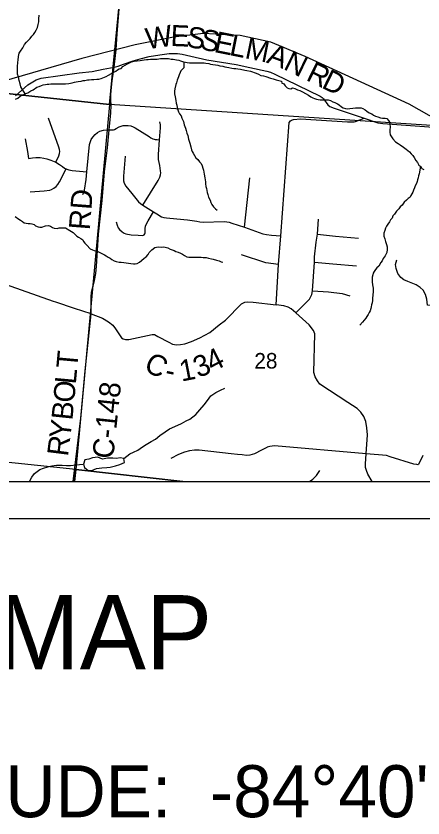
# Model space of a CAD drawing. Extents: x 0 to 34, y 0 to 22.
# Drawn here: x 5.92 to 7.016, y 13.194 to 15.353 of the extents above; entities that cross this region are included whole.
import ezdxf

# ---------------------------------------------------------------- set-up
doc = ezdxf.new("R2010")
doc.units = 0
for name, color, linetype in [('Default', 7, 'Continuous'), ('GM_X_County_Road', 7, 'Continuous'), ('GM_X_County_Road_Text', 7, 'Continuous'), ('GM_X_Minor_Lake', 7, 'Continuous'), ('GM_X_Minor_River', 7, 'Continuous'), ('GM_X_Rail_Line', 7, 'Continuous'), ('GM_X_Section', 7, 'Continuous'), ('GM_X_Section_Text', 7, 'Continuous'), ('GM_X_State_Route', 7, 'Continuous'), ('GM_X_Township_Road', 7, 'Continuous'), ('SH_Data', 7, 'Continuous'), ('SH_Text', 7, 'Continuous')]:
    doc.layers.add(name, color=color, linetype=linetype)

msp = doc.modelspace()

# ---------------------------------------------------------------- linework, layer by layer
at = {"layer": 'Default'}
for points in [[(6.3691, 14.1), (7.0916, 14.1), (7.1496, 15.0512), (6.1715, 15.1151), (6.0802, 14.1319)], [(5.0677, 14.1), (6.0771, 14.1), (6.0802, 14.1319), (5.0822, 14.236)], [(6.0771, 14.1), (6.3691, 14.1), (6.0802, 14.1319)]]:
    msp.add_lwpolyline(points, close=True, dxfattribs=at)
at = {"layer": 'GM_X_County_Road'}
for points in [[(6.1223, 14.5512), (6.122, 14.5815), (6.1219, 14.5974), (6.1229, 14.6095), (6.1261, 14.6238), (6.1306, 14.6408), (6.1344, 14.6594), (6.1364, 14.6792), (6.139, 14.7219), (6.1416, 14.7661), (6.1513, 14.8563), (6.1574, 14.9337), (6.1655, 14.9978), (6.1706, 15.047), (6.1746, 15.0922), (6.1756, 15.112), (6.1752, 15.1286), (6.175, 15.1473), (6.1758, 15.1569), (6.1768, 15.1663), (6.1837, 15.2151), (6.1889, 15.2618), (6.1923, 15.305), (6.1982, 15.3827)], [(6.1837, 15.2151), (6.1945, 15.218), (6.2094, 15.2237), (6.2348, 15.2322), (6.2536, 15.2382), (6.2778, 15.2439), (6.3068, 15.2486), (6.3324, 15.2518), (6.3429, 15.2523), (6.3542, 15.2518), (6.367, 15.2507), (6.3903, 15.2447), (6.4333, 15.2349), (6.5127, 15.2229), (6.549, 15.2147), (6.5954, 15.2048), (6.6052, 15.2022), (6.6164, 15.1966), (6.7389, 15.1368), (6.7445, 15.134), (6.7479, 15.1305), (6.7592, 15.1142), (6.7651, 15.1091), (6.7768, 15.105), (6.8572, 15.078), (6.8942, 15.0655), (6.9074, 15.0636), (7.0696, 15.0521)], [(5.9183, 15.1385), (5.9517, 15.1682), (5.9737, 15.1813), (5.9868, 15.1855), (6.0896, 15.2002), (6.1243, 15.2039), (6.1539, 15.2098), (6.1837, 15.2151)], [(6.62, 14.5755), (6.6265, 14.6841), (6.6333, 14.7609), (6.6554, 15.0661), (6.659, 15.0706), (6.6619, 15.0729), (6.6667, 15.0741), (6.6861, 15.0762), (6.8128, 15.0683), (6.8303, 15.0685), (6.8341, 15.0693), (6.8572, 15.078)], [(6.1223, 14.5512), (6.1526, 14.5392), (6.1683, 14.5301), (6.1802, 14.5207), (6.1879, 14.5106), (6.2032, 14.487), (6.2081, 14.4835), (6.2141, 14.4822), (6.2232, 14.4819), (6.2866, 14.4958), (6.2927, 14.4953), (6.3016, 14.4905), (6.3308, 14.4745), (6.3413, 14.4697), (6.3515, 14.4675), (6.3622, 14.4684), (6.374, 14.4704), (6.392, 14.4767), (6.4143, 14.4864), (6.4416, 14.5005), (6.467, 14.5212), (6.4839, 14.5344), (6.5273, 14.5781), (6.5359, 14.5823), (6.5432, 14.5834), (6.5585, 14.5822), (6.62, 14.5755)], [(6.8786, 14.1), (6.8673, 14.1199), (6.8638, 14.1291), (6.8614, 14.1372), (6.861, 14.1474), (6.8629, 14.1744), (6.8665, 14.2251), (6.8649, 14.2445), (6.862, 14.2613), (6.8564, 14.2748), (6.8488, 14.2864), (6.8381, 14.2963), (6.8136, 14.3122), (6.7375, 14.3622), (6.7314, 14.3711), (6.7254, 14.3816), (6.7215, 14.3934), (6.7242, 14.4977), (6.7211, 14.5064), (6.7092, 14.5214), (6.6736, 14.554), (6.6607, 14.565), (6.6527, 14.5691), (6.6414, 14.5728), (6.62, 14.5755)], [(6.0736, 14.1), (6.0945, 14.2699), (6.1055, 14.3973), (6.1223, 14.5512)]]:
    msp.add_lwpolyline(points, dxfattribs=at)
at = {"layer": 'GM_X_Minor_Lake'}
for points in [[(6.1526, 14.1602), (6.1401, 14.1651), (6.1257, 14.1636), (6.1157, 14.1597), (6.1046, 14.1577), (6.1009, 14.1463)], [(6.1009, 14.1464), (6.1041, 14.1372), (6.1141, 14.129), (6.124, 14.1298), (6.1367, 14.1348), (6.1504, 14.1364), (6.1637, 14.1371), (6.1733, 14.1388), (6.1874, 14.1422), (6.1989, 14.1453), (6.2116, 14.1511), (6.2096, 14.1618), (6.1998, 14.1632), (6.1898, 14.1615), (6.18, 14.1622), (6.1663, 14.1622), (6.1526, 14.1602)]]:
    msp.add_lwpolyline(points, dxfattribs=at)
at = {"layer": 'GM_X_Minor_River'}
for points in [[(5.9444, 15.1434), (5.9325, 15.162), (5.9305, 15.1704), (5.9282, 15.1796), (5.9258, 15.1892), (5.9238, 15.1969), (5.9234, 15.206), (5.9234, 15.2166), (5.9242, 15.2291), (5.9251, 15.2344), (5.9262, 15.2443), (5.9284, 15.2529), (5.9312, 15.2581), (5.9376, 15.2678), (5.9425, 15.276), (5.948, 15.2826), (5.9528, 15.2882), (5.9575, 15.2926), (5.9622, 15.2985), (5.967, 15.3036), (5.9706, 15.3085), (5.9742, 15.3152), (5.9775, 15.3223), (5.9793, 15.3298), (5.9807, 15.3374), (5.9813, 15.3453), (5.982, 15.3555)], [(5.9185, 15.1294), (5.9246, 15.1319), (5.9309, 15.137), (5.939, 15.1412), (5.9459, 15.144), (5.9509, 15.1465), (5.9598, 15.1512), (5.9656, 15.1544), (5.9757, 15.1613), (5.9815, 15.163), (5.9877, 15.1658), (5.993, 15.1675), (5.9988, 15.1684), (6.0037, 15.1694), (6.0083, 15.1696), (6.0136, 15.1702), (6.0212, 15.1703), (6.0258, 15.1702), (6.0307, 15.1704), (6.0368, 15.1705), (6.0455, 15.1706), (6.0531, 15.1707), (6.0615, 15.1712), (6.0703, 15.1732), (6.0772, 15.1745), (6.0818, 15.1754), (6.0871, 15.1768), (6.0948, 15.178), (6.1001, 15.179), (6.1047, 15.1796), (6.112, 15.1812), (6.1165, 15.1815), (6.1226, 15.182), (6.1295, 15.1822), (6.1371, 15.1827), (6.1424, 15.1828), (6.1485, 15.1845), (6.1578, 15.1884), (6.1624, 15.1901), (6.1686, 15.1937), (6.1763, 15.198), (6.1814, 15.2009), (6.188, 15.2048), (6.1926, 15.2081), (6.1976, 15.2106), (6.2026, 15.2119), (6.2074, 15.2171), (6.2132, 15.2211), (6.2201, 15.2246), (6.2255, 15.2267), (6.231, 15.2299)], [(6.231, 15.2299), (6.2382, 15.2316), (6.2455, 15.2321), (6.2542, 15.2333), (6.2596, 15.2339), (6.2649, 15.2352), (6.271, 15.2358), (6.2756, 15.236), (6.2821, 15.2365), (6.2881, 15.2367), (6.2931, 15.2365), (6.2995, 15.2371), (6.3041, 15.2377), (6.3091, 15.2383), (6.3155, 15.2388), (6.3307, 15.2383), (6.3371, 15.2373), (6.3432, 15.2367), (6.3519, 15.2353), (6.3579, 15.2339), (6.3628, 15.2322), (6.3681, 15.2309), (6.376, 15.2291), (6.3809, 15.2278), (6.3869, 15.2272), (6.3918, 15.2267), (6.399, 15.2268), (6.4055, 15.2269), (6.4142, 15.227), (6.426, 15.2266), (6.4309, 15.2261), (6.4388, 15.225), (6.4434, 15.2237), (6.4498, 15.2228), (6.4566, 15.2214), (6.4634, 15.2204), (6.4686, 15.2187), (6.4762, 15.2177), (6.4822, 15.2159), (6.4932, 15.2144), (6.5007, 15.2126), (6.5064, 15.2117), (6.5117, 15.2115), (6.517, 15.2109), (6.5245, 15.2095), (6.5358, 15.2072), (6.5415, 15.2063), (6.5513, 15.2044), (6.5562, 15.2027), (6.5614, 15.2007), (6.5667, 15.199), (6.573, 15.1968), (6.579, 15.1932), (6.5865, 15.1918), (6.5926, 15.1901), (6.6049, 15.1855), (6.6121, 15.1841), (6.6204, 15.1815), (6.6271, 15.1798), (6.635, 15.1776), (6.6352, 15.1723), (6.6401, 15.171), (6.6445, 15.1651), (6.6496, 15.16), (6.6541, 15.1579), (6.6594, 15.157), (6.664, 15.1595), (6.6704, 15.1581), (6.6775, 15.1545), (6.6843, 15.1523), (6.6914, 15.1491), (6.6992, 15.1446), (6.7074, 15.1398), (6.7133, 15.1358), (6.7189, 15.1329), (6.7234, 15.1309), (6.729, 15.1295), (6.7336, 15.1286), (6.7392, 15.1277), (6.7442, 15.1271), (6.7495, 15.1273), (6.7552, 15.1275), (6.7601, 15.1273), (6.7669, 15.1256), (6.7728, 15.1223), (6.7781, 15.1198), (6.7852, 15.1162), (6.79, 15.1137), (6.7967, 15.1089), (6.8011, 15.1061), (6.8068, 15.1037), (6.8132, 15.1027), (6.8185, 15.1036), (6.8265, 15.1049), (6.8338, 15.1061), (6.8448, 15.1061), (6.8494, 15.106), (6.8542, 15.1043), (6.8598, 15.1003), (6.8646, 15.0967), (6.8705, 15.092)], [(6.3715, 15.2301), (6.3715, 15.2135), (6.3634, 15.2056), (6.3617, 15.2007), (6.3589, 15.1951), (6.3575, 15.1895), (6.3534, 15.1801), (6.3517, 15.1733), (6.35, 15.1685), (6.3477, 15.1571), (6.3463, 15.1511), (6.3468, 15.1435), (6.3481, 15.1351), (6.35, 15.1259), (6.3513, 15.1183), (6.3526, 15.1129), (6.3539, 15.1064), (6.3556, 15.1006), (6.3569, 15.0953), (6.3602, 15.0898), (6.3645, 15.0844), (6.3658, 15.0783), (6.3705, 15.069), (6.3728, 15.0602), (6.3759, 15.0509), (6.3776, 15.0444), (6.38, 15.0379), (6.3824, 15.0309), (6.3844, 15.0214), (6.3875, 15.011), (6.3901, 15.0007), (6.3925, 14.993), (6.3943, 14.9884), (6.3964, 14.9837), (6.4007, 14.9775), (6.4039, 14.9709), (6.4091, 14.9666), (6.4134, 14.9607), (6.4182, 14.956), (6.4207, 14.9495), (6.4227, 14.9433), (6.4241, 14.9383), (6.4264, 14.9276), (6.4283, 14.9177), (6.4292, 14.9123), (6.4298, 14.907), (6.43, 14.9013), (6.4309, 14.8936), (6.4322, 14.8887), (6.4332, 14.8829), (6.4345, 14.8776), (6.4366, 14.8722), (6.4382, 14.8649), (6.4422, 14.8572), (6.4442, 14.851), (6.4471, 14.846), (6.4514, 14.8394), (6.4566, 14.8342), (6.4613, 14.8299)], [(6.8705, 15.092), (6.8776, 15.0894), (6.8828, 15.0862), (6.8877, 15.0838), (6.8941, 15.0813), (6.9012, 15.0791), (6.9065, 15.0782), (6.9137, 15.0776), (6.9186, 15.077), (6.923, 15.0719), (6.9255, 15.0673), (6.9268, 15.0608), (6.927, 15.0554), (6.9266, 15.0448), (6.9268, 15.0399), (6.9277, 15.0334), (6.9306, 15.028), (6.935, 15.0225), (6.9419, 15.0143), (6.9486, 15.0099), (6.9545, 15.0062), (6.963, 15.0002), (6.9704, 14.9947), (6.9752, 14.9907), (6.9797, 14.9875), (6.9841, 14.9824), (6.9888, 14.9773), (6.9921, 14.9719), (6.9967, 14.9641), (7.0015, 14.9586), (7.005, 14.9517), (7.0098, 14.9477), (7.0131, 14.9423), (7.0179, 14.9398)], [(7.0089, 14.9485), (7.0057, 14.9281), (7.0037, 14.9225), (7.0027, 14.9172), (7.001, 14.9123), (7.0001, 14.9074), (6.998, 14.9022), (6.9952, 14.8962), (6.9931, 14.8902), (6.9902, 14.8842), (6.9885, 14.8789), (6.9861, 14.8745), (6.9829, 14.8696), (6.9816, 14.8651), (6.9757, 14.8615), (6.9714, 14.8571), (6.9655, 14.8516), (6.96, 14.8442), (6.9545, 14.8394), (6.9509, 14.8339), (6.9446, 14.8273), (6.939, 14.8198), (6.935, 14.815), (6.9326, 14.8091), (6.9282, 14.8046), (6.9254, 14.799), (6.9214, 14.7927), (6.9177, 14.7868), (6.9149, 14.7815), (6.9132, 14.7759), (6.9107, 14.7684), (6.91, 14.7601), (6.9128, 14.7531), (6.9152, 14.7458), (6.9176, 14.7378), (6.9189, 14.7316), (6.9194, 14.724), (6.918, 14.7165), (6.9139, 14.7071), (6.9087, 14.7005), (6.9058, 14.6937), (6.9019, 14.6893), (6.8966, 14.6796), (6.8915, 14.6752), (6.8879, 14.6708), (6.8843, 14.6652), (6.8815, 14.6607), (6.8806, 14.6562), (6.8792, 14.6498), (6.8787, 14.6445), (6.8788, 14.6377), (6.8797, 14.6293), (6.8807, 14.6247), (6.8813, 14.6201), (6.8813, 14.6117), (6.881, 14.6011), (6.8799, 14.5932), (6.8794, 14.5871), (6.8788, 14.5807), (6.8774, 14.5754), (6.8765, 14.5701), (6.8752, 14.5656), (6.8739, 14.5595), (6.8707, 14.5547), (6.8686, 14.5498), (6.8642, 14.5443), (6.8618, 14.5394), (6.857, 14.5339), (6.8527, 14.5284), (6.8456, 14.521)], [(5.9171, 14.813), (5.9267, 14.8058), (5.9315, 14.803), (5.9367, 14.7994), (5.9416, 14.7966), (5.9465, 14.7953), (5.9518, 14.7947), (5.9578, 14.7945), (5.9624, 14.7936), (5.968, 14.7915), (5.9724, 14.7879), (5.9788, 14.785), (5.9833, 14.7845), (5.989, 14.7847), (5.999, 14.7881), (6.0066, 14.7894), (6.0126, 14.7876), (6.0182, 14.7837), (6.0227, 14.7816), (6.0303, 14.7813), (6.036, 14.7823), (6.0406, 14.7825), (6.047, 14.7827), (6.0527, 14.7825), (6.0646, 14.776), (6.0732, 14.77), (6.0787, 14.7645), (6.0831, 14.7605), (6.0879, 14.7577), (6.0943, 14.754), (6.0995, 14.7508), (6.1016, 14.7462), (6.1052, 14.7415), (6.11, 14.736), (6.1195, 14.7266), (6.1255, 14.7237), (6.13, 14.722), (6.1379, 14.7195), (6.1454, 14.7166), (6.1524, 14.7125), (6.158, 14.7101), (6.1625, 14.7072), (6.1681, 14.704), (6.1729, 14.7012), (6.1777, 14.6976), (6.1837, 14.6943), (6.1897, 14.6922), (6.1972, 14.6905), (6.2025, 14.6899), (6.2097, 14.6893), (6.2162, 14.6887), (6.2226, 14.6877), (6.2286, 14.6867), (6.2358, 14.6857), (6.2404, 14.6856)], [(6.2404, 14.6856), (6.2461, 14.6865), (6.2523, 14.6905), (6.2574, 14.6948), (6.2648, 14.7007), (6.2699, 14.7047), (6.2758, 14.7109), (6.2782, 14.7165), (6.2853, 14.7235), (6.2931, 14.7301), (6.2977, 14.7311), (6.3031, 14.7316), (6.3103, 14.731), (6.3163, 14.7312), (6.3213, 14.731), (6.3284, 14.7285), (6.3344, 14.7252), (6.3404, 14.7235), (6.3456, 14.7218), (6.3501, 14.719), (6.3561, 14.7176), (6.3625, 14.7148), (6.3681, 14.7119), (6.3732, 14.7079), (6.38, 14.705), (6.3849, 14.7041), (6.3898, 14.7036), (6.3974, 14.7037), (6.4035, 14.7039), (6.413, 14.7035), (6.4179, 14.7034), (6.4236, 14.7032), (6.4319, 14.7025), (6.4376, 14.7012), (6.4462, 14.6997), (6.4508, 14.6984), (6.4594, 14.6958), (6.4665, 14.6937), (6.4725, 14.6916), (6.477, 14.6899)], [(6.2096, 14.1618), (6.2265, 14.1743), (6.2361, 14.179), (6.2473, 14.1844), (6.2601, 14.1935), (6.2705, 14.1997), (6.284, 14.2073), (6.2949, 14.2138), (6.3069, 14.2234), (6.3209, 14.2332), (6.3333, 14.2412), (6.3556, 14.2512), (6.3652, 14.2555), (6.3775, 14.2628), (6.3879, 14.2678), (6.4039, 14.2803), (6.4145, 14.2929), (6.4259, 14.3059), (6.435, 14.3178), (6.4444, 14.3304), (6.4576, 14.3392), (6.4699, 14.3453), (6.4823, 14.351)], [(5.9562, 14.1), (5.957, 14.1014), (5.9618, 14.1112), (5.9697, 14.1216), (5.9837, 14.1318), (5.9933, 14.1358), (6.0052, 14.1392), (6.0159, 14.1416), (6.0281, 14.1439), (6.0437, 14.1438), (6.0551, 14.1431), (6.0664, 14.1428), (6.0813, 14.1443), (6.0908, 14.1455), (6.1009, 14.1464)], [(6.7097, 14.1), (6.719, 14.1063), (6.7288, 14.1155), (6.7383, 14.1293)]]:
    msp.add_lwpolyline(points, dxfattribs=at)
at = {"layer": 'GM_X_Rail_Line'}
msp.add_lwpolyline([(7.0591, 15.07), (6.9789, 15.1159), (6.6986, 15.2444), (6.606, 15.2829), (6.5231, 15.3006), (6.4237, 15.3057), (6.344, 15.296), (6.2408, 15.2754), (6.0967, 15.239), (5.8513, 15.1677), (5.7896, 15.155), (5.5397, 15.125), (5.4524, 15.1186), (5.3669, 15.1328), (5.3004, 15.1455), (5.2587, 15.1606), (5.2248, 15.1914), (5.2119, 15.2431), (5.2148, 15.3086), (5.2164, 15.3989)], dxfattribs=at)
at = {"layer": 'GM_X_Section'}
for points in [[(6.268, 16.1109), (6.1715, 15.1151), (5.1838, 15.2208), (5.2813, 16.2088)], [(7.2064, 16.0507), (7.1496, 15.0512), (6.1715, 15.1151), (6.268, 16.1109)], [(6.1715, 15.1151), (6.0802, 14.1319), (5.0822, 14.236), (5.1838, 15.2208)]]:
    msp.add_lwpolyline(points, close=True, dxfattribs=at)
at = {"layer": 'GM_X_State_Route'}
msp.add_lwpolyline([(5.2499, 15.926), (5.1715, 15.1469), (5.1456, 14.8898), (5.1035, 14.4713), (5.0661, 14.1), (8.9, 14.1), (8.9, 16.8616)], dxfattribs=at)
at = {"layer": 'GM_X_Township_Road'}
msp.add_line((6.5346, 14.7843), (6.5494, 14.917), dxfattribs=at)
for points in [[(6.0268, 14.9598), (6.0346, 14.9764), (6.0363, 14.983), (6.0372, 14.9881), (6.0363, 14.9936), (6.0351, 14.9998), (6.0067, 15.0776)], [(6.1706, 15.047), (6.1798, 15.0465), (6.1825, 15.0469), (6.1851, 15.0479), (6.1892, 15.0501), (6.1974, 15.0545), (6.2031, 15.0567), (6.2085, 15.058), (6.2148, 15.0586), (6.222, 15.0583), (6.2285, 15.057), (6.2348, 15.055), (6.2406, 15.0518), (6.2778, 15.0282), (6.283, 15.0252), (6.2883, 15.0225), (6.2915, 15.0214), (6.2946, 15.0208), (6.2997, 15.0202), (6.3058, 15.02)], [(6.2615, 14.8441), (6.3025, 14.9104), (6.3067, 14.919), (6.3088, 14.9255), (6.3096, 14.9307), (6.3089, 14.9365), (6.3067, 14.9509), (6.3036, 14.9665), (6.303, 14.9735), (6.3031, 14.9803), (6.3058, 15.02), (6.3088, 15.0523), (6.3086, 15.0602), (6.3067, 15.0679)], [(6.0995, 14.8728), (6.104, 14.8844), (6.1088, 14.9133), (6.1103, 14.9335), (6.1177, 15.0073), (6.1222, 15.0207), (6.126, 15.0269), (6.1323, 15.0338), (6.1388, 15.0392), (6.1457, 15.043), (6.1552, 15.046), (6.1644, 15.0469), (6.1706, 15.047)], [(5.9439, 15.0222), (5.9501, 14.9883), (5.9531, 14.9695), (5.9635, 14.971), (5.9733, 14.9722), (5.9841, 14.9719), (5.9945, 14.9701), (6.0025, 14.9683), (6.0137, 14.9652), (6.0268, 14.9598), (6.0369, 14.9536), (6.0445, 14.9481), (6.0501, 14.9438), (6.0542, 14.9415), (6.0562, 14.9405), (6.0619, 14.9386), (6.0708, 14.9369), (6.1103, 14.9335)], [(6.2138, 14.9757), (6.2091, 14.9222), (6.2087, 14.9162), (6.2091, 14.9092), (6.2111, 14.903), (6.2155, 14.8949), (6.2313, 14.8753), (6.2494, 14.8529), (6.2545, 14.8483), (6.2615, 14.8441), (6.2896, 14.826), (6.303, 14.8177), (6.3043, 14.8167), (6.3116, 14.8128), (6.3175, 14.8107), (6.3252, 14.8094), (6.3719, 14.8056), (6.3811, 14.8045), (6.4064, 14.8005), (6.415, 14.7988), (6.4239, 14.7984), (6.4802, 14.7998), (6.4874, 14.7992), (6.4938, 14.7979), (6.5007, 14.7955), (6.5346, 14.7843), (6.5848, 14.7669), (6.5939, 14.7645), (6.6074, 14.7627), (6.6333, 14.7609)], [(5.9579, 14.8794), (5.9951, 14.8827), (6.0103, 14.8842), (6.0151, 14.8856), (6.0216, 14.8895), (6.0273, 14.8943), (6.0321, 14.8996), (6.0365, 14.9065), (6.0542, 14.9415)], [(6.1896, 14.7993), (6.1924, 14.7901), (6.195, 14.7829), (6.1983, 14.7782), (6.2055, 14.7716), (6.2107, 14.7681), (6.2157, 14.7662), (6.23, 14.764), (6.2489, 14.7632), (6.2607, 14.7625), (6.2644, 14.7638), (6.2661, 14.7664), (6.2672, 14.7697), (6.2676, 14.7742), (6.2677, 14.7812), (6.2687, 14.7875), (6.27, 14.7917), (6.2751, 14.8017), (6.2896, 14.826)], [(6.6736, 14.554), (6.6963, 14.577), (6.7097, 14.5911), (6.7161, 14.6033), (6.7179, 14.6134), (6.7232, 14.6903), (6.7239, 14.705), (6.7281, 14.7441), (6.7315, 14.7654), (6.7341, 14.8061)], [(6.7315, 14.7654), (6.7799, 14.7607), (6.8417, 14.755)], [(6.6265, 14.6841), (6.5924, 14.6887), (6.5267, 14.7103)], [(6.7232, 14.6903), (6.7732, 14.6862), (6.8369, 14.6808)], [(7.1209, 14.5382), (7.1119, 14.5452), (7.1047, 14.5522), (7.0986, 14.5608), (7.09, 14.5668), (7.0814, 14.5704), (7.0283, 14.5749), (7.0261, 14.5904), (7.0225, 14.6034), (7.0164, 14.6145), (7.0086, 14.6225), (6.9975, 14.6297), (6.9751, 14.638), (6.964, 14.6424), (6.956, 14.6488), (6.9482, 14.6596), (6.9433, 14.6729), (6.9422, 14.6842), (6.945, 14.6969)], [(6.0271, 14.5822), (6.0207, 14.5844), (5.8908, 14.6304)], [(6.7179, 14.6134), (6.7616, 14.6103), (6.7979, 14.6058), (6.8187, 14.5995)], [(6.1223, 14.5512), (6.077, 14.5653), (6.0271, 14.5822)], [(6.5955, 14.1914), (6.5809, 14.1845), (6.5616, 14.174), (6.5494, 14.171), (6.54, 14.1702), (6.5291, 14.1713), (6.5159, 14.1721), (6.4992, 14.1744), (6.4125, 14.1845), (6.3999, 14.1842), (6.3866, 14.1824), (6.3736, 14.1792), (6.357, 14.1728), (6.3366, 14.1619)], [(7.0152, 14.1694), (7.0038, 14.1459), (7.0031, 14.1453), (7.0021, 14.145), (6.9993, 14.1453), (6.9914, 14.1467), (6.9275, 14.1665), (6.9174, 14.1695), (6.8629, 14.1744), (6.6162, 14.1957), (6.6033, 14.1941), (6.5965, 14.1918), (6.5955, 14.1914)]]:
    msp.add_lwpolyline(points, dxfattribs=at)
at = {"layer": 'SH_Data'}
for p, q in [((2.1, 14.1), (8.9, 14.1)), ((2, 14), (9, 14))]:
    msp.add_line(p, q, dxfattribs=at)

# ---------------------------------------------------------------- texts
at = {"layer": 'GM_X_County_Road_Text'}
for s, height, rotation, p in [('W', 0.0568, 8.251, (6.2726, 15.2632)), ('E', 0.0568, 357.6294, (6.335, 15.2725)), ('S', 0.0568, 349.5749, (6.3754, 15.271)), ('S', 0.0568, 348.6749, (6.4128, 15.2641)), ('E', 0.0568, 348.6548, (6.4504, 15.2566)), ('L', 0.0568, 348.6548, (6.4921, 15.2482)), ('M', 0.0568, 348.5557, (6.5337, 15.2399)), ('A', 0.0568, 339.2167, (6.5918, 15.2283)), ('N', 0.0568, 334.0076, (6.6373, 15.2111)), ('R', 0.0568, 333.9588, (6.698, 15.1815)), ('D', 0.0568, 333.9555, (6.7399, 15.161)), ('RD', 0.05682, 85.6443, (6.1183, 14.7755)), ('T', 0.0568, 84.8278, (6.0844, 14.4024)), ('4', 0.0568, 26.6858, (6.4483, 14.3934)), ('C', 0.0568, 332.6696, (6.2606, 14.4007)), ('1', 0.0568, 10.8746, (6.3651, 14.3687)), ('3', 0.0568, 21.0854, (6.4101, 14.3783)), ('L', 0.0568, 84.8271, (6.0805, 14.3601)), ('-', 0.0568, 348.2783, (6.3179, 14.3736)), ('O', 0.0568, 84.797, (6.076, 14.3102)), ('C-148', 0.05682, 83.9636, (6.1812, 14.1592)), ('B', 0.0568, 84.1512, (6.0712, 14.2631)), ('Y', 0.0568, 83.1719, (6.0651, 14.2124)), ('R', 0.0568, 82.8755, (6.0593, 14.1658))]:
    msp.add_text(s, height=height, rotation=rotation, dxfattribs=at).set_placement(p)
at = {"layer": 'GM_X_Section_Text'}
msp.add_text('28', height=0.04186, rotation=0, dxfattribs=at).set_placement((6.5615, 14.4039))
at = {"layer": 'SH_Text'}
for s, height, p in [('LOCATION MAP', 0.2, (4.4269, 13.5938)), ('LATITUDE:  39°13\'10"     LONGITUDE:  -84°40\'05"', 0.14, (3.071, 13.1959))]:
    msp.add_text(s, height=height, dxfattribs=at).set_placement(p)

doc.saveas('drawing.dxf')
